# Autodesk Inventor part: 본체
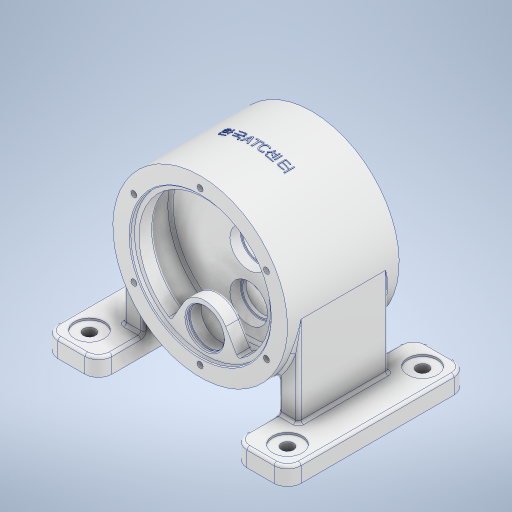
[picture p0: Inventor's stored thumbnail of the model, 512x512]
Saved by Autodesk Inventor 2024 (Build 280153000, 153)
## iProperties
Created: 2025-12
Part Number: 본체
Material: 알루미늄 6061
Document SubType Name: Modeling
Designer: Eud07
Density: 2.7 g/cm^3
Appearance: 알루미늄 - 평지
Mass: 5626.86 g
Surface Area: 3057.42 cm^2
Volume: 2084.02 cm^3
Author: Eud07
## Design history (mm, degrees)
sketch "스케치1"
  geometry: L1 (-97, -62)-(97, -62); L2 (97, -62)-(97, 62); L3 (97, 62)-(-97, 62); L4 (-97, 62)-(-97, -62); L5 (-97, -62)-(97, 62); L6 (97, -62)-(-97, 62); L7 (0, 62)-(0, -62); L8 (78, 62)-(78, 57); L9 (78, 57)-(73, 57); L10 (73, 57)-(73, 40); L11 (73, 40)-(87, 40); L12 (87, 40)-(87, 8); L13 (87, 8)-(0, 8); L14 (97, 0)-(0, 0); L15 (78, -62)-(78, -57); L16 (78, -57)-(73, -57); L17 (73, -57)-(73, -40); L18 (73, -40)-(87, -40); L19 (87, -40)-(87, -8); L20 (87, -8)-(0, -8); 2 further points
  constraints: 40 end point, 7 symmetric about line, 6 perpendicular, 5 midpoint, 2 horizontal, 2 parallel, 2 point on line, 1 vertical
  dimensions: "d0" = 124 distance of L1.end L2.end; "d1" = 97 distance between parallel lines of L7 L2; "d2" = 22 distance between parallel lines of L11 L3; "d3" = 5 distance of L8.start L8.end; "d4" = 32 distance of L11.end L12.end; "d5" = 78 distance between parallel lines of L7 L8; "d6" = 73 distance between parallel lines of L7 L10; "d7" = 87 distance between parallel lines of L7 L12
revolve "회전1" sketch "스케치1" stored, may be unused: angle "d8" = 90 deg
feature "면 삭제1"
sketch "스케치2" dims "d10" = 54
  geometry: L1 (-23.383, -39)-(-61.06, -104.259); L2 (0, 0)-(0, -116.93); L3 (23.383, -39)-(61.06, -104.259); C1 r 73 at (0, 0); 5 further points
  constraints: 6 end point, 2 symmetric about line, 1 centre point, 1 coincident, 1 vertical, 1 vertical alignment, 4 other
  dimensions: "d9" = 146 diameter of C1; "d11" = 52.5 distance of point (0, -52.5) point (0, 0); "d12" = 30 deg angle of L2 L1
extrude "돌출1" cut sketch "스케치2" distance "d13" = 17; taper "d14" = 0 deg
sketch "스케치3"
  geometry: C1 r 21 at (0, 0); C2 r 21 at (0, -52.5); C3 r 19 at (0, 0); C4 r 19 at (0, -52.5); A1 r 27 centre (0, -52.5) between (23.383, -39) and (-23.383, -39) reference; 1 further point
  constraints: 4 centre point, 3 coincident, 1 concentric
  dimensions: "d15" = 42 diameter of C1; "d16" = 42 diameter of C2; "d17" = 38 diameter of C3; "d18" = 38 diameter of C4
extrude "돌출2" cut sketch "스케치3" distance "d19" = 66; taper "d20" = 0 deg
extrude "돌출3" cut sketch "스케치3" extent not by distance; stored distance "d21" = 0; taper "d22" = 0 deg
sketch "스케치4"
  geometry: L1 (-52.5, 76.931)-(-52.5, 27.612); L2 (-87, 8)-(87, 8) reference; L3 (-73.5, 57)-(-31.5, 57) reference; L4 (-31.5, 57)-(-31.5, 40) reference; L5 (-31.5, 53.95)-(-30.25, 53.95); L6 (-30.25, 53.95)-(-30.25, 52); L7 (-30.25, 52)-(-31.5, 52); L8 (-31.5, 52)-(-31.5, 53.95); L9 (-39, 40)-(-25.5, 40) reference; 2 further points
  constraints: 10 end point, 2 parallel, 2 perpendicular, 1 horizontal, 1 point on line
  dimensions: "d23" = 21 distance from line of L3.end L1; "d24" = 1.95 distance of L5.end L6.end; "d25" = 12 distance between parallel lines of L9 L7; "d26" = 22.25 distance between parallel lines of L1 L6
revolve "회전2" sketch "스케치4" stored, may be unused: angle "d27" = 90 deg
node "작업 평면1"
sketch "스케치6"
  geometry: L1 (135, -100)-(75, -100); L2 (75, -100)-(75, 100); L3 (75, 100)-(135, 100); L4 (135, 100)-(135, -100); L5 (135, -100)-(75, 100); L6 (75, -100)-(135, 100); L7 (75, -50)-(97, -50); L8 (97, -50)-(97, 50); L9 (97, 50)-(75, 50); L10 (75, 50)-(75, -50); 3 further points
  constraints: 20 end point, 4 parallel, 2 horizontal, 2 midpoint, 2 perpendicular, 1 horizontal alignment, 1 point on line
  dimensions: "d29" = 60 distance of L2.end L3.end; "d30" = 75 distance from line of point (0, 0) L2; "d31" = 200 distance of L3.end L1.start; "d32" = 22 distance of L8.end L9.end; "d33" = 100 distance of L7.end L8.end; "d34" = 50 distance from line of point (0, 0) L7
extrude "돌출4" join sketch "스케치6" distance "d35" = 20; taper "d36" = 0 deg
extrude "돌출5" join sketch "스케치6" stored distance "d37" = 20; taper "d38" = 0 deg
fillet "모깎기1" dims "d39" = 15
sketch "스케치7"
  geometry: L1 (-135, 85)-(-135, -85) reference; L2 (73, -57)-(-73, -57) reference; 6 further points
  constraints: 2 midpoint
  dimensions: "d40" = 75 vertical distance of point (-135, 0) point (-110, 75); "d41" = 110 horizontal distance of point (0, -57) point (-110, 75)
hole "구멍1" sketch "스케치7" at (-110, 75) diameter "d42" = 13.5; stored, may be unused: countersink angle "d46" = 90 deg, drill point angle "d48" = 118 deg; dims "d43" = 6, "d44" = 33, "d45" = 2, "d47" = 8
sketch "스케치8"
  geometry: L1 (-75, -120)-(-75, -100) reference; L2 (-75, -112)-(-36.6, -89.83); L3 (-75, -100)-(-75, -61.514) reference; L4 (-75, -120)-(-90, -120) reference; A1 r 97 centre (0, 0) between (-36.6, -89.83) and (-75, -61.514) reference; 2 further points
  constraints: 2 end point, 1 coincident, 1 point on circle, 1 point on line
  dimensions: "d49" = 60 deg angle of L2 L3; "d50" = 8 distance from line of L4 point (-75, -112)
feature "리브1" sketch "스케치8" dims "d51" = 1, "d52" = 12, "d53" = 0, "d54" = 0, "d55" = 1, "d56" = 1
sketch "스케치9"
  geometry: 2 further points
  constraints: 1 vertical alignment
  dimensions: "d57" = 85 distance of point (0, 0) point (0, 85)
hole "구멍2" sketch "스케치9" at (0, 85) diameter "d58" = 6.647; stored, may be unused: countersink angle "d62" = 90 deg, drill point angle "d64" = 118 deg; dims "d59" = 16, "d60" = 33, "d61" = 2, "d63" = 18
node "작업 평면2"
sketch "스케치10"
  geometry: 2 further points
  constraints: 1 coincident, 1 other
feature "엠보싱1" sketch "스케치10" dims "d0" = 124, "d1" = 97, "d2" = 22, "d3" = 5, "d4" = 32, "d5" = 78, "d6" = 73, "d7" = 87, "d69" = 0.5, "d70" = 0
fillet "모깎기2" dims "d71" = 0.6
fillet "모깎기3" dims "d72" = 3
fillet "모깎기4" dims "d73" = 3
fillet "모깎기5" dims "d74" = 3
chamfer "모따기1" distance "d75" = 1; stored, may be unused: second distance "d76" = 2, angle "d77" = 45 deg
fillet "모깎기6" dims "d78" = 3
fillet "모깎기7" dims "d79" = 3
chamfer "모따기2" distance "d80" = 1; stored, may be unused: second distance "d81" = 2, angle "d82" = 45 deg
node "솔리드1"
mirror "미러1"
mirror "미러2"
pattern_circular "원형 패턴1" dims angle "d66" = 360 deg
mirror "미러3"
feature "A9D066F2-1C7D-4E18-AEED-F7BC21143FA4" dims "d58" = 6.647, "d59" = 16, "d60" = 33, "d61" = 2, "d62" = 90 deg, "d63" = 18, "d64" = 118 deg
other parameters: "d68" = 160.25
